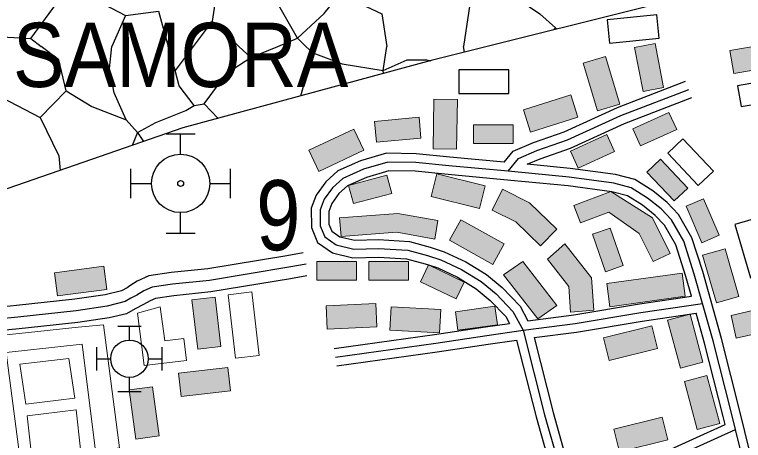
# Model space of a CAD drawing. Extents: x -64005 to -55000, y -89025 to -80000.
# Drawn here: x -63391 to -62767, y -80656 to -80291 of the extents above; entities that cross this region are included whole.
import ezdxf
from ezdxf.enums import TextEntityAlignment as Align

# ---------------------------------------------------------------- set-up
doc = ezdxf.new("R2010")
doc.units = 0
doc.header["$LTSCALE"] = 32
doc.linetypes.add('DOT_DASHED', pattern=[7.7, 5, -1.2, 0.3, -1.2])
doc.linetypes.add('LONG_DASHED', pattern=[7.5, 6, -1.5])
for name, color, linetype, lineweight in [('16', 7, 'Continuous', 25), ('19', 7, 'Continuous', 25), ('21', 7, 'Continuous', 25), ('39', 7, 'LONG_DASHED', 25), ('41', 7, 'Continuous', 25), ('7', 7, 'Continuous', 13), ('8', 7, 'Continuous', 25)]:
    doc.layers.add(name, color=color, linetype=linetype, lineweight=lineweight)
doc.layers.add('36', color=7, linetype='Continuous')
doc.layers.add('37', color=7, linetype='Continuous')

msp = doc.modelspace()

# ---------------------------------------------------------------- hatches: boundary and pattern name
at = {"layer": '7'}
for points in [[(-62835.57, -80353.9), (-62842.84, -80316.34), (-62860.51, -80319.77), (-62853.23, -80357.32)], [(-62737, -80314.99), (-62778.87, -80322.29), (-62775.44, -80341.99), (-62733.57, -80334.69)], [(-62872.98, -80368.05), (-62885.35, -80327.39), (-62904.48, -80333.21), (-62892.11, -80373.87)], [(-62949.47, -80392.16), (-62908.94, -80379.37), (-62914.95, -80360.3), (-62955.48, -80373.09)], [(-63012.67, -80406.71), (-63012, -80364.22), (-63032, -80363.91), (-63032.67, -80406.4)], [(-62831.06, -80375.2), (-62862.01, -80389.29), (-62855.38, -80403.86), (-62824.43, -80389.77)], [(-63081.19, -80400.82), (-63043.11, -80397.22), (-63044.81, -80379.29), (-63082.89, -80382.9)], [(-62964.26, -80385.91), (-62998.26, -80385.91), (-62998.26, -80401.91), (-62964.26, -80401.91)], [(-63100.57, -80389.45), (-63138.99, -80407.64), (-63130.43, -80425.71), (-63092.01, -80407.52)], [(-62884.3, -80394.17), (-62915.25, -80408.26), (-62908.62, -80422.83), (-62877.67, -80408.74)], [(-62814.92, -80439.97), (-62838.28, -80415.27), (-62849.9, -80426.27), (-62826.54, -80450.97)], [(-63072.23, -80429.02), (-63105.07, -80437.82), (-63100.93, -80453.28), (-63068.09, -80444.48)], [(-63034.38, -80447.31), (-62993.13, -80457.55), (-62988.32, -80438.13), (-63029.56, -80427.89)], [(-62973.46, -80441.02), (-62950.36, -80452.52), (-62926.87, -80475.01), (-62940.77, -80489.4), (-62962.04, -80468.93), (-62982.26, -80458.99)], [(-62912.41, -80454.91), (-62880.73, -80442.95), (-62845.04, -80465.31), (-62830.08, -80495.84), (-62844.44, -80502.89), (-62856.42, -80478.97), (-62882.44, -80460.56), (-62906.7, -80469.85)], [(-62788.17, -80480.42), (-62801.62, -80449.19), (-62816.31, -80455.52), (-62802.86, -80486.75)], [(-63111.32, -80481.52), (-63112.68, -80465.58), (-63062.9, -80461.61), (-63028.74, -80467.59), (-63031.27, -80483.73), (-63063.86, -80477.72)], [(-63018.7, -80484.57), (-62981.58, -80505.28), (-62971.84, -80487.8), (-63008.95, -80467.1)], [(-62870.09, -80506.29), (-62881.31, -80474.19), (-62896.41, -80479.47), (-62885.19, -80511.57)], [(-62919.96, -80487.63), (-62897.34, -80516.73), (-62895.28, -80544.57), (-62915.24, -80546.06), (-62916.79, -80524.18), (-62934.93, -80500.9)], [(-62771.17, -80532.68), (-62783.08, -80491.88), (-62802.27, -80497.48), (-62790.36, -80538.28)], [(-63314.47, -80506.9), (-63356.61, -80512.44), (-63354.01, -80532.26), (-63311.87, -80526.72)], [(-63098.3, -80502.8), (-63132.3, -80502.8), (-63132.3, -80518.8), (-63098.3, -80518.8)], [(-63053.81, -80502.72), (-63087.81, -80502.72), (-63087.81, -80518.72), (-63053.81, -80518.72)], [(-63006.05, -80520.39), (-63036.71, -80505.68), (-63043.63, -80520.11), (-63012.97, -80534.82)], [(-62926.88, -80540.47), (-62956.14, -80502.71), (-62972.57, -80514.12), (-62943.3, -80551.89)], [(-62819.81, -80512.76), (-62884.23, -80521.69), (-62881.52, -80541.51), (-62817.1, -80532.58)], [(-63239.12, -80535.75), (-63234.1, -80577.95), (-63214.24, -80575.59), (-63219.26, -80533.39)], [(-63081.77, -80538.78), (-63124.22, -80540.79), (-63123.27, -80560.77), (-63080.82, -80558.76)], [(-63026.09, -80543.96), (-63068.52, -80541.53), (-63069.67, -80561.5), (-63027.24, -80563.93)], [(-62980.05, -80541.09), (-63013.72, -80545.82), (-63011.49, -80561.66), (-62977.81, -80556.93)], [(-62736.49, -80539.42), (-62777.91, -80548.95), (-62773.43, -80568.44), (-62732.01, -80558.91)], [(-62801.97, -80589.04), (-62812.97, -80547.99), (-62832.29, -80553.16), (-62821.29, -80594.21)], [(-62845.75, -80557.95), (-62886.98, -80568.26), (-62882.13, -80587.67), (-62840.9, -80577.36)], [(-63208.36, -80593.59), (-63250.59, -80598.4), (-63248.32, -80618.27), (-63206.09, -80613.46)], [(-62787.56, -80641.36), (-62798.56, -80600.31), (-62817.88, -80605.48), (-62806.88, -80646.53)], [(-63292.71, -80612.7), (-63286.91, -80654.81), (-63267.09, -80652.08), (-63272.89, -80609.97)], [(-62836.83, -80636.06), (-62878.06, -80646.37), (-62873.21, -80665.78), (-62831.98, -80655.47)]]:
    msp.add_hatch(color=256, dxfattribs=at).paths.add_polyline_path(points)

# ---------------------------------------------------------------- linework, layer by layer
at = {"layer": '16'}
for p, q in [((-63302.44, -80558.04), (-63282.44, -80558.04)), ((-63292.44, -80570.04), (-63292.44, -80558.04)), ((-63320.44, -80596.04), (-63320.44, -80576.04)), ((-63264.44, -80596.04), (-63264.44, -80576.04)), ((-63320.44, -80586.04), (-63308.44, -80586.04)), ((-63276.44, -80586.04), (-63264.44, -80586.04)), ((-63292.44, -80614.04), (-63292.44, -80602.04)), ((-63302.44, -80614.04), (-63282.44, -80614.04))]:
    msp.add_line(p, q, dxfattribs=at)
for points in [[(-62883.9, -80295.86), (-62881.9, -80316.02), (-62839.36, -80311.8), (-62841.36, -80291.65)], [(-63010.65, -80338.75), (-63010.65, -80359), (-62967.9, -80359), (-62967.9, -80338.75)], [(-62772.34, -80352.55), (-62769.25, -80370.28), (-62731.82, -80363.75), (-62734.91, -80346.02)], [(-62806, -80437.76), (-62792.92, -80425.39), (-62819.04, -80397.78), (-62832.12, -80410.15)], [(-62761.31, -80516.8), (-62739.71, -80510.49), (-62753.03, -80464.9), (-62774.63, -80471.21)]]:
    msp.add_lwpolyline(points, close=True, dxfattribs=at)
msp.add_circle((-63292.44, -80586.04), 16, dxfattribs=at)
at = {"layer": '19'}
for p, q in [((-63000.4, -80276.33), (-63006.81, -80318.73)), ((-63221.82, -80297.05), (-63198.82, -80318.73)), ((-62928.19, -80302.77), (-62926.91, -80303.89)), ((-63148.73, -80311.58), (-63141.48, -80318.73)), ((-63005.88, -80323.72), (-63006.81, -80318.73)), ((-63075.19, -80341.96), (-63075.38, -80339.48)), ((-63216.49, -80380.35), (-63228.65, -80367.9)), ((-63285.47, -80392.33), (-63280.36, -80400.22))]:
    msp.add_line(p, q, dxfattribs=at)
msp.add_lwpolyline([(-63440.41, -80264.85), (-63183.05, -80214.91), (-62822.26, -80143.2), (-62509.98, -80086.29), (-62491.79, -80084.77), (-62450.85, -80187.13), (-62456.91, -80195.47), (-62573.63, -80224.68), (-62813.91, -80275.52), (-63034.47, -80330.9), (-63246.7, -80388.56), (-63446.03, -80457.59), (-63476.37, -80352.95), (-63430.13, -80328.68)], close=True, dxfattribs=at)
for points in [[(-63148.73, -80311.58), (-63125.83, -80290.44), (-63112.62, -80273.7), (-63116.45, -80215.08)], [(-63257.5, -80233.16), (-63214.78, -80252.11), (-63221.82, -80297.05), (-63237.94, -80318.73)], [(-63165.67, -80318.73), (-63148.73, -80311.58), (-63177.35, -80261.36), (-63214.78, -80252.11)], [(-63376.9, -80312.03), (-63361.05, -80290.44), (-63343.88, -80266.9)], [(-63343.88, -80266.9), (-63295.8, -80292.2), (-63307.66, -80318.73)], [(-63112.62, -80273.7), (-63076.52, -80290.89), (-63072.35, -80318.73)], [(-62959.01, -80278.54), (-62941.4, -80290.89), (-62928.19, -80302.77), (-62929.8, -80304.62)], [(-63295.8, -80292.2), (-63267.62, -80288.68), (-63259.21, -80318.73)], [(-63411.24, -80309.83), (-63376.9, -80312.03), (-63368.06, -80318.73)], [(-63368.92, -80379.46), (-63346.73, -80356.8), (-63352.93, -80330.16), (-63368.06, -80318.73)], [(-63295.23, -80381.67), (-63305.45, -80358.58), (-63309.43, -80337.71), (-63307.66, -80318.73)], [(-63237.94, -80318.73), (-63253.38, -80339.48), (-63259.21, -80318.73)], [(-63198.82, -80318.73), (-63188.57, -80328.36), (-63165.67, -80318.73)], [(-63145.88, -80361.17), (-63135.75, -80324.37), (-63141.48, -80318.73)], [(-63135.75, -80324.37), (-63110.43, -80333.71), (-63075.38, -80339.48), (-63072.35, -80318.73)], [(-63285.47, -80392.33), (-63269.93, -80383.89), (-63244.19, -80373.67), (-63237.09, -80369.23), (-63228.65, -80367.9), (-63209, -80341.26), (-63188.57, -80328.36)], [(-63075.38, -80339.48), (-63054.97, -80330.16), (-63038.09, -80330.16), (-63034.8, -80330.99)], [(-63237.09, -80369.23), (-63249.83, -80352.36), (-63253.38, -80339.48)], [(-63346.73, -80356.8), (-63324.53, -80370.12), (-63295.23, -80381.67), (-63285.47, -80392.33), (-63290.18, -80403.62)], [(-63402.04, -80362.13), (-63368.92, -80379.46), (-63352.93, -80412.31), (-63351.61, -80424.89)]]:
    msp.add_lwpolyline(points, dxfattribs=at)
at = {"layer": '21'}
for points in [[(-62971.9, -80417.79), (-62964.24, -80408.52), (-62946.81, -80400.85), (-62920.71, -80391.77), (-62874.98, -80370.97), (-62816.82, -80348.53)], [(-62952.28, -80419.65), (-62941.31, -80414.83), (-62915.13, -80405.71), (-62869.18, -80384.81), (-62811.42, -80362.53)], [(-62971.9, -80417.79), (-63018.52, -80413.52), (-63047.21, -80410.56), (-63072.53, -80410.15), (-63094.97, -80416.69), (-63114.11, -80425.34), (-63124.46, -80434.6), (-63132.73, -80445.91), (-63137, -80457.3), (-63136.77, -80473.74), (-63131.63, -80486.61), (-63118.76, -80495.52), (-63101.27, -80499.67), (-63079.59, -80499.09), (-63055.49, -80500.53), (-63039.58, -80504.82), (-63036.57, -80505.71), (-63028.85, -80508.37), (-63012, -80516.34), (-62995.96, -80526.08), (-62984.01, -80536.06), (-62970.6, -80550), (-62967.48, -80555.78)], [(-62768.49, -80994.83), (-62767.93, -80949.75), (-62766.24, -80918.73), (-62761.36, -80872.32), (-62752.67, -80819.37), (-62749.98, -80795.15), (-62748.23, -80769.23), (-62749.01, -80740.29), (-62751.92, -80709.47), (-62758.1, -80680.7), (-62770.07, -80631.96), (-62786.01, -80568.74), (-62802.17, -80511.38), (-62811.37, -80482.44), (-62822.84, -80462.58), (-62832.7, -80452.28), (-62844.97, -80442.43), (-62860.33, -80432.67), (-62876.87, -80428.38), (-62915.53, -80423.18), (-62952.28, -80419.65)], [(-62811.81, -80532.5), (-62816.55, -80515.68), (-62825.17, -80488.54), (-62834.92, -80471.64), (-62842.86, -80463.36), (-62853.71, -80454.65), (-62866.39, -80446.59), (-62879.77, -80443.12), (-62917.25, -80438.08), (-62966.34, -80433.37), (-63019.98, -80428.44), (-63048.11, -80425.54), (-63070.51, -80425.19), (-63089.75, -80430.79), (-63105.83, -80438.06), (-63113.28, -80444.72), (-63119.41, -80453.11), (-63121.96, -80459.92), (-63121.81, -80470.76), (-63119.37, -80476.85), (-63112.54, -80481.58), (-63099.71, -80484.63), (-63079.35, -80484.07), (-63053.07, -80485.65), (-63035.26, -80490.44), (-63023.27, -80494.43), (-63004.88, -80503.12), (-62987.2, -80513.84), (-62973.77, -80525.08), (-62958.38, -80541.08), (-62951.64, -80553.54)], [(-62951.64, -80553.54), (-62912.37, -80548.35), (-62856.18, -80539.16), (-62811.81, -80532.5)], [(-62946.43, -80567.98), (-62910.17, -80563.19), (-62853.86, -80553.98), (-62807.71, -80547.06)], [(-62782.99, -80642.26), (-62784.63, -80635.58), (-62800.51, -80572.6), (-62807.71, -80547.06)], [(-63117.26, -80577.36), (-63031.48, -80565.23), (-62987.93, -80558.78), (-62967.48, -80555.78)], [(-62946.43, -80567.98), (-62930.16, -80631.98), (-62915.39, -80684.38), (-62911.5, -80692.31), (-62910.02, -80693.78), (-62908.67, -80694.23), (-62905.11, -80693.88), (-62891.41, -80689.84), (-62845.67, -80670.7), (-62810.55, -80654.83), (-62782.99, -80642.26)], [(-63115.16, -80592.22), (-63029.34, -80580.07), (-62985.75, -80573.62), (-62961.38, -80570.05)], [(-62961.38, -80570.05), (-62944.64, -80635.86), (-62929.45, -80689.76), (-62923.86, -80701.15), (-62918.14, -80706.88), (-62910.41, -80709.47), (-62902.23, -80708.68), (-62886.37, -80704), (-62846.23, -80687.2)]]:
    msp.add_lwpolyline(points, dxfattribs=at)
at = {"layer": '39', "linetype": 'DOT_DASHED'}
for points in [[(-62968.64, -80425.63), (-62959.59, -80414.67), (-62944.06, -80407.84), (-62917.92, -80398.74), (-62872.08, -80377.89), (-62814.12, -80355.53)], [(-62968.64, -80425.63), (-63019.25, -80420.98), (-63047.66, -80418.05), (-63071.52, -80417.67), (-63092.36, -80423.74), (-63109.97, -80431.7), (-63118.87, -80439.66), (-63126.07, -80449.51), (-63129.48, -80458.61), (-63129.29, -80472.25), (-63125.5, -80481.73), (-63115.65, -80488.55), (-63100.49, -80492.15), (-63079.47, -80491.58), (-63054.28, -80493.09), (-63037.42, -80497.63), (-63026.06, -80501.4), (-63008.44, -80509.73), (-62991.58, -80519.96), (-62978.89, -80530.57), (-62964.49, -80545.54), (-62955.78, -80561.65)], [(-62802.28, -80538.66), (-62809.36, -80513.53), (-62818.27, -80485.49), (-62828.88, -80467.11), (-62837.78, -80457.82), (-62849.34, -80448.54), (-62863.36, -80439.63), (-62878.32, -80435.75), (-62916.39, -80430.63), (-62965.64, -80425.9), (-62968.64, -80425.63)], [(-62955.78, -80561.65), (-62911.27, -80555.77), (-62855.02, -80546.57), (-62802.28, -80538.66)], [(-62774.22, -80646.51), (-62777.35, -80633.77), (-62793.26, -80570.67), (-62802.28, -80538.66)], [(-63116.21, -80584.79), (-63030.41, -80572.65), (-62986.84, -80566.2), (-62955.78, -80561.65)], [(-62955.78, -80561.65), (-62937.4, -80633.92), (-62922.42, -80687.07), (-62917.68, -80696.73), (-62914.08, -80700.33), (-62909.54, -80701.85), (-62903.67, -80701.28), (-62888.89, -80696.92), (-62842.68, -80677.58), (-62839.7, -80676.23)], [(-62839.7, -80676.23), (-62807.45, -80661.66), (-62774.22, -80646.51)], [(-62776.13, -81006.38), (-62775.43, -80949.5), (-62773.72, -80918.13), (-62768.8, -80871.32), (-62760.1, -80818.35), (-62757.45, -80794.48), (-62755.74, -80769.08), (-62756.5, -80740.74), (-62759.35, -80710.61), (-62765.41, -80682.38), (-62774.22, -80646.51)]]:
    msp.add_lwpolyline(points, dxfattribs=at)
at = {"layer": '39'}
msp.add_lwpolyline([(-63141.19, -80505.11), (-63156.26, -80507.71), (-63224.13, -80518.95), (-63255.66, -80522.22), (-63273.05, -80524.76), (-63280.3, -80528.02), (-63286.24, -80531.59), (-63291.29, -80534.26), (-63296.24, -80537.07), (-63311.46, -80541.08), (-63337.92, -80545.07), (-63387.93, -80550.52), (-63428.98, -80554.53)], dxfattribs=at)
at = {"layer": '41'}
for p, q in [((-63261.16, -80393.49), (-63236.16, -80393.49)), ((-63248.66, -80410.99), (-63248.66, -80393.49)), ((-63291.16, -80448.49), (-63291.16, -80423.49)), ((-63206.16, -80448.49), (-63206.16, -80423.49)), ((-63291.16, -80435.99), (-63273.66, -80435.99)), ((-63223.66, -80435.99), (-63206.16, -80435.99)), ((-63248.66, -80478.49), (-63248.66, -80460.99)), ((-63261.16, -80478.49), (-63236.16, -80478.49))]:
    msp.add_line(p, q, dxfattribs=at)
for radius in [25, 2.5]:
    msp.add_circle((-63248.66, -80435.99), radius, dxfattribs=at)
at = {"layer": '7'}
for points in [[(-62835.57, -80353.9), (-62842.84, -80316.34), (-62860.51, -80319.77), (-62853.23, -80357.32)], [(-62737, -80314.99), (-62778.87, -80322.29), (-62775.44, -80341.99), (-62733.57, -80334.69)], [(-62872.98, -80368.05), (-62885.35, -80327.39), (-62904.48, -80333.21), (-62892.11, -80373.87)], [(-62949.47, -80392.16), (-62908.94, -80379.37), (-62914.95, -80360.3), (-62955.48, -80373.09)], [(-63012.67, -80406.71), (-63012, -80364.22), (-63032, -80363.91), (-63032.67, -80406.4)], [(-62831.06, -80375.2), (-62862.01, -80389.29), (-62855.38, -80403.86), (-62824.43, -80389.77)], [(-63081.19, -80400.82), (-63043.11, -80397.22), (-63044.81, -80379.29), (-63082.89, -80382.9)], [(-62964.26, -80385.91), (-62998.26, -80385.91), (-62998.26, -80401.91), (-62964.26, -80401.91)], [(-63100.57, -80389.45), (-63138.99, -80407.64), (-63130.43, -80425.71), (-63092.01, -80407.52)], [(-62884.3, -80394.17), (-62915.25, -80408.26), (-62908.62, -80422.83), (-62877.67, -80408.74)], [(-62814.92, -80439.97), (-62838.28, -80415.27), (-62849.9, -80426.27), (-62826.54, -80450.97)], [(-63072.23, -80429.02), (-63105.07, -80437.82), (-63100.93, -80453.28), (-63068.09, -80444.48)], [(-63034.38, -80447.31), (-62993.13, -80457.55), (-62988.32, -80438.13), (-63029.56, -80427.89)], [(-62973.46, -80441.02), (-62950.36, -80452.52), (-62926.87, -80475.01), (-62940.77, -80489.4), (-62962.04, -80468.93), (-62982.26, -80458.99)], [(-62912.41, -80454.91), (-62880.73, -80442.95), (-62845.04, -80465.31), (-62830.08, -80495.84), (-62844.44, -80502.89), (-62856.42, -80478.97), (-62882.44, -80460.56), (-62906.7, -80469.85)], [(-62788.17, -80480.42), (-62801.62, -80449.19), (-62816.31, -80455.52), (-62802.86, -80486.75)], [(-63111.32, -80481.52), (-63112.68, -80465.58), (-63062.9, -80461.61), (-63028.74, -80467.59), (-63031.27, -80483.73), (-63063.86, -80477.72)], [(-63018.7, -80484.57), (-62981.58, -80505.28), (-62971.84, -80487.8), (-63008.95, -80467.1)], [(-62870.09, -80506.29), (-62881.31, -80474.19), (-62896.41, -80479.47), (-62885.19, -80511.57)], [(-62919.96, -80487.63), (-62897.34, -80516.73), (-62895.28, -80544.57), (-62915.24, -80546.06), (-62916.79, -80524.18), (-62934.93, -80500.9)], [(-62771.17, -80532.68), (-62783.08, -80491.88), (-62802.27, -80497.48), (-62790.36, -80538.28)], [(-63314.47, -80506.9), (-63356.61, -80512.44), (-63354.01, -80532.26), (-63311.87, -80526.72)], [(-63098.3, -80502.8), (-63132.3, -80502.8), (-63132.3, -80518.8), (-63098.3, -80518.8)], [(-63053.81, -80502.72), (-63087.81, -80502.72), (-63087.81, -80518.72), (-63053.81, -80518.72)], [(-63006.05, -80520.39), (-63036.71, -80505.68), (-63043.63, -80520.11), (-63012.97, -80534.82)], [(-62926.88, -80540.47), (-62956.14, -80502.71), (-62972.57, -80514.12), (-62943.3, -80551.89)], [(-62819.81, -80512.76), (-62884.23, -80521.69), (-62881.52, -80541.51), (-62817.1, -80532.58)], [(-63187.9, -80528.91), (-63181.6, -80583.14), (-63201.78, -80585.49), (-63208.08, -80531.25)], [(-63239.12, -80535.75), (-63234.1, -80577.95), (-63214.24, -80575.59), (-63219.26, -80533.39)], [(-63285.57, -80546.95), (-63279.95, -80591.82), (-63243.7, -80587.5), (-63245.94, -80568.62), (-63262.34, -80570.57), (-63266.18, -80541.68)], [(-63081.77, -80538.78), (-63124.22, -80540.79), (-63123.27, -80560.77), (-63080.82, -80558.76)], [(-63026.09, -80543.96), (-63068.52, -80541.53), (-63069.67, -80561.5), (-63027.24, -80563.93)], [(-62980.05, -80541.09), (-63013.72, -80545.82), (-63011.49, -80561.66), (-62977.81, -80556.93)], [(-62736.49, -80539.42), (-62777.91, -80548.95), (-62773.43, -80568.44), (-62732.01, -80558.91)], [(-62801.97, -80589.04), (-62812.97, -80547.99), (-62832.29, -80553.16), (-62821.29, -80594.21)], [(-63385.74, -80674.52), (-63397.96, -80580.73), (-63332.82, -80573.7), (-63321.36, -80665.25), (-63301.08, -80662.27), (-63314.67, -80557.15), (-63336.37, -80559.07), (-63386.69, -80564.56), (-63415.19, -80567.33), (-63406.16, -80626.28), (-63400.64, -80676.24)], [(-62845.75, -80557.95), (-62886.98, -80568.26), (-62882.13, -80587.67), (-62840.9, -80577.36)], [(-63386.28, -80590.72), (-63381.08, -80624.91), (-63339.07, -80619.76), (-63344.22, -80585.83)], [(-63208.36, -80593.59), (-63250.59, -80598.4), (-63248.32, -80618.27), (-63206.09, -80613.46)], [(-62787.56, -80641.36), (-62798.56, -80600.31), (-62817.88, -80605.48), (-62806.88, -80646.53)], [(-63292.71, -80612.7), (-63286.91, -80654.81), (-63267.09, -80652.08), (-63272.89, -80609.97)], [(-63380.06, -80634.86), (-63337.91, -80629.76), (-63334.2, -80663.3), (-63376.35, -80668.41)], [(-62836.83, -80636.06), (-62878.06, -80646.37), (-62873.21, -80665.78), (-62831.98, -80655.47)]]:
    msp.add_lwpolyline(points, close=True, dxfattribs=at)
at = {"layer": '8', "linetype": 'LONG_DASHED'}
msp.add_lwpolyline([(-63143.8, -80495.41), (-63157.93, -80497.85), (-63225.46, -80509.03), (-63256.9, -80512.29), (-63275.88, -80515.07), (-63285.91, -80519.58), (-63292.22, -80523.65), (-63294.28, -80525.29), (-63299.32, -80527.81), (-63313.16, -80531.22), (-63339.21, -80535.15), (-63388.96, -80540.57), (-63423.02, -80543.89)], dxfattribs=at)
at = {"layer": '8'}
msp.add_lwpolyline([(-63140.88, -80515.21), (-63154.59, -80517.57), (-63222.8, -80528.87), (-63254.42, -80532.15), (-63270.21, -80534.45), (-63274.68, -80536.46), (-63280.54, -80539.54), (-63287.6, -80543.43), (-63294.93, -80547.58), (-63309.76, -80550.94), (-63336.63, -80554.99), (-63386.9, -80560.47), (-63419.99, -80563.69)], dxfattribs=at)

# ---------------------------------------------------------------- texts
at = {"layer": '36', "width": 0.9}
msp.add_text('SAMORA', height=55, dxfattribs=at).set_placement((-63248.67, -80353.49), align=Align.CENTER)
at = {"layer": '37', "width": 0.85}
msp.add_text('9', height=60, dxfattribs=at).set_placement((-63165.14, -80493.2), align=Align.CENTER)

doc.saveas('drawing.dxf')
